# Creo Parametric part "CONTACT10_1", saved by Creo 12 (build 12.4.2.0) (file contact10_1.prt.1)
Units: Custom; MM, KILOGRAM, SECS

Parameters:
  PTC_WM_ITERATION = "0"
  PTC_WM_VERSION = "-.0"
  PTC_WM_LIFECYCLE_STATE = "In Work"
  PTC_WM_LIFECYCLE = "MO_CADDocument"
  PTC_WM_CREATED_BY = "Maximilian Roepper (Z0017RMS: MO)"
  PTC_WM_CREATED_ON = "18-Sep-26 11:36:42 AM"
  PTC_WM_MODIFIED_BY = "Maximilian Roepper (Z0017RMS: MO)"
  PTC_WM_MODIFIED_ON = "18-Sep-26 11:36:46 AM"
  PDMLINKNUMBER = "PDM000071455037"
  PTC_WM_NAME = "contact10_1.prt"
  PTC_WM_NUMBER = "PDM000071455037"

Other parameters: WEIGHT, WEIGHT_FACTOR, WEIGHT_ADD, _MASS_TEMP, _DIFF_TEMP, MC_ERRORS, SUPPLIER

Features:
  1. coordinate system
  2. datum plane "PRT_YZ"
  3. datum plane "PRT_XY"
  4. datum plane "PRT_XZ"
  5. coordinate system
  6. datum axis
  7. datum axis
  8. datum axis
  9. coordinate system
  10. imported feature

Other named items: PRT, SIEMENS_MO, DRW_VIEW_ORG, PRT_X, PRT_Y, PRT_Z, CS0, ROUGH_GROB

Layers: 00_STD_CSYS-KSYS, 01_STD_PLANES-EBENEN, 02_STD_AXES-ACHSEN, 03_STD_CSYS-KSYS, 24_IMPORT_FEAT-IMPORT_KE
